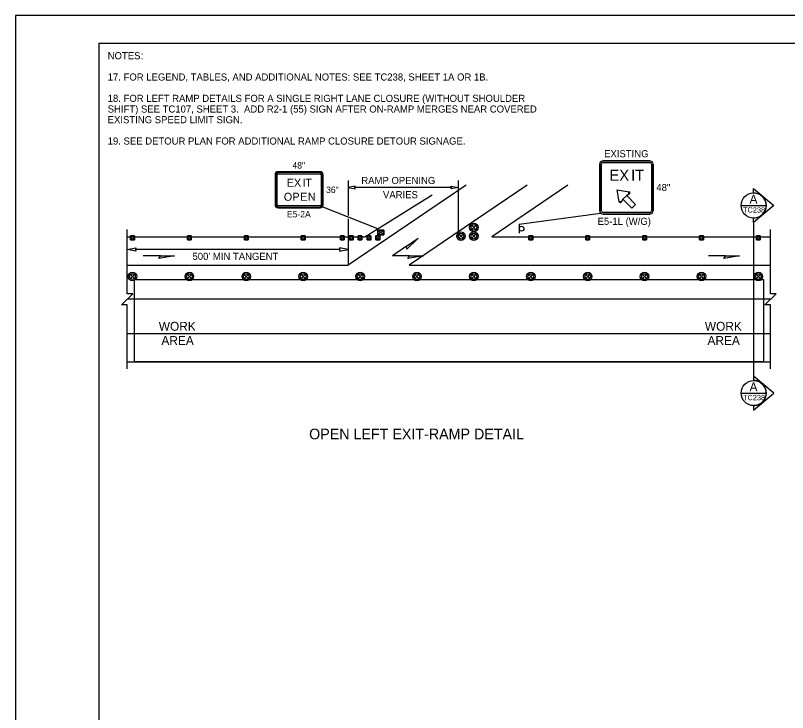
# Model space of a CAD drawing. Extents: x 99999 to 100116, y 99995 to 100013.
# Drawn here: x 100079.06 to 100087.75, y 100002.85 to 100010.69 of the extents above; entities that cross this region are included whole.
import ezdxf

# ---------------------------------------------------------------- set-up
doc = ezdxf.new("R2010")
doc.units = 0
for name, color, linetype in [('RD_MK_LineEdgeYellow', 7, 'Continuous'), ('RD_MK_LineLane', 7, 'Continuous'), ('SH_DE_DetailHeading2Text', 7, 'Continuous'), ('SH_GI_GeneralNotesBodyText', 7, 'Continuous'), ('SH_GI_PlotLimits', 7, 'Continuous'), ('SH_GI_SheetBorder', 7, 'Continuous'), ('SH_TI_WZSectionCut', 7, 'Continuous'), ('TR_SN_ConstructionSigns', 7, 'Continuous'), ('TR_WZ_PortableSignMount5ftMinBlk-Org', 7, 'Continuous'), ('TR_WZ_TrafficCone', 7, 'Continuous'), ('TR_WZ_TrafficSafetyDrum', 7, 'Continuous'), ('TR_WZ_WorkAreaLabel', 7, 'Continuous'), ('TR_WZ_WorkZoneDetails', 7, 'Continuous'), ('TR_WZ_WorkZoneTextCurrent', 7, 'Continuous')]:
    doc.layers.add(name, color=color, linetype=linetype)

msp = doc.modelspace()

# ---------------------------------------------------------------- linework, layer by layer
at = {"layer": 'RD_MK_LineEdgeYellow'}
for p, q in [((100084.1333, 100008.7784), (100082.8064, 100007.8789)), ((100080.32, 100007.8789), (100082.8064, 100007.8789)), ((100084.4209, 100007.8789), (100087.555, 100007.8789)), ((100080.32, 100007.1109), (100087.555, 100007.1109))]:
    msp.add_line(p, q, dxfattribs=at)
at = {"layer": 'RD_MK_LineLane'}
msp.add_lwpolyline([(100087.555, 100007.4949), (100080.32, 100007.4949)], dxfattribs=at)
at = {"layer": 'SH_GI_PlotLimits'}
msp.add_lwpolyline([(100079.0625, 99999.6875), (100096.0625, 99999.6875), (100096.0625, 100010.6875), (100079.0625, 100010.6875)], close=True, dxfattribs=at)
at = {"layer": 'SH_GI_SheetBorder'}
for q in [(100080, 100000), (100095.75, 100010.375)]:
    msp.add_line((100080, 100010.375), q, dxfattribs=at)
at = {"layer": 'SH_TI_WZSectionCut'}
for p, q in [((100087.3657, 100008.6913), (100087.3657, 100008.7412)), ((100087.3657, 100008.7412), (100087.5938, 100008.55)), ((100087.5938, 100008.55), (100087.3657, 100008.3589)), ((100087.3657, 100008.3589), (100087.3657, 100008.4088)), ((100087.3657, 100008.3589), (100087.3657, 100006.6309)), ((100087.3657, 100006.6309), (100087.3657, 100006.581)), ((100087.5939, 100006.4398), (100087.3657, 100006.6309)), ((100087.3657, 100006.2486), (100087.5939, 100006.4398)), ((100087.3657, 100006.2985), (100087.3657, 100006.2486))]:
    msp.add_line(p, q, dxfattribs=at)
for points in [[(100087.2245, 100008.5501), (100087.5069, 100008.5501)], [(100087.2245, 100006.4398), (100087.5069, 100006.4398)]]:
    msp.add_lwpolyline(points, dxfattribs=at)
for centre in [(100087.3657, 100008.55), (100087.3657, 100006.4398)]:
    msp.add_circle(centre, 0.1412, dxfattribs=at)
for centre in [(100087.3657, 100008.55), (100087.3657, 100006.4398)]:
    msp.add_arc(centre, 0.1412, 269.99779, 90.00221, dxfattribs=at)
at = {"layer": 'TR_SN_ConstructionSigns'}
for p, q in [((100085.6712, 100009.0522), (100086.1962, 100009.0522)), ((100086.1962, 100009.0522), (100085.6712, 100009.0522)), ((100086.1962, 100009.0522), (100085.6712, 100009.0522)), ((100086.1962, 100009.0522), (100085.6712, 100009.0522)), ((100086.1962, 100009.0522), (100085.6712, 100009.0522)), ((100085.6712, 100009.0335), (100086.1962, 100009.0335)), ((100086.1962, 100009.0522), (100086.1962, 100009.0522)), ((100085.6337, 100008.4897), (100085.6337, 100009.0147)), ((100085.6337, 100009.0147), (100085.6337, 100009.0147)), ((100085.6337, 100009.0147), (100085.6337, 100008.4897)), ((100085.6337, 100009.0147), (100085.6337, 100008.4897)), ((100085.6337, 100009.0147), (100085.6337, 100008.4897)), ((100085.6337, 100009.0147), (100085.6337, 100008.4897)), ((100085.6525, 100008.4897), (100085.6525, 100009.0147)), ((100086.215, 100009.0147), (100086.215, 100008.4897)), ((100086.2337, 100009.0147), (100086.2337, 100008.4897)), ((100086.2337, 100008.4897), (100086.2337, 100009.0147)), ((100086.2337, 100008.4897), (100086.2337, 100009.0147)), ((100086.2337, 100008.4897), (100086.2337, 100009.0147)), ((100086.2337, 100008.4897), (100086.2337, 100009.0147)), ((100081.983, 100008.8955), (100081.983, 100008.558)), ((100081.9914, 100008.8955), (100081.9914, 100008.558)), ((100082.0055, 100008.558), (100082.0055, 100008.8955)), ((100082.4893, 100008.9292), (100082.0168, 100008.9292)), ((100082.4893, 100008.9208), (100082.0168, 100008.9208)), ((100082.0168, 100008.9067), (100082.4893, 100008.9067)), ((100082.5005, 100008.8955), (100082.5005, 100008.558)), ((100082.5146, 100008.558), (100082.5146, 100008.8955)), ((100082.523, 100008.558), (100082.523, 100008.8955)), ((100085.8293, 100008.7277), (100085.9652, 100008.7029)), ((100085.8541, 100008.5918), (100085.8293, 100008.7277)), ((100085.9688, 100008.68), (100085.9376, 100008.6614)), ((100085.9652, 100008.7029), (100085.9624, 100008.6907)), ((100085.9624, 100008.6907), (100085.9652, 100008.7029)), ((100085.9624, 100008.6907), (100085.9688, 100008.68)), ((100085.9688, 100008.68), (100085.9624, 100008.6907)), ((100085.8663, 100008.5946), (100085.8541, 100008.5918)), ((100085.8541, 100008.5918), (100085.8663, 100008.5946)), ((100085.8771, 100008.5882), (100085.8663, 100008.5946)), ((100085.8663, 100008.5946), (100085.8771, 100008.5882)), ((100085.8956, 100008.6195), (100085.8771, 100008.5882)), ((100085.8956, 100008.6195), (100085.9376, 100008.6614)), ((100085.9376, 100008.6614), (100085.8956, 100008.6195)), ((100085.9961, 100008.5189), (100085.8956, 100008.6195)), ((100085.9376, 100008.6614), (100086.0381, 100008.5609)), ((100082.4893, 100008.5467), (100082.0168, 100008.5467)), ((100082.0168, 100008.5327), (100082.4893, 100008.5327)), ((100082.0168, 100008.5242), (100082.4893, 100008.5242)), ((100086.0381, 100008.5609), (100085.9961, 100008.5189)), ((100086.1962, 100008.471), (100085.6712, 100008.471)), ((100086.1962, 100008.4522), (100085.6712, 100008.4522)), ((100085.6712, 100008.4522), (100085.6712, 100008.4522)), ((100085.6712, 100008.4522), (100086.1962, 100008.4522)), ((100085.6712, 100008.4522), (100086.1962, 100008.4522)), ((100085.6712, 100008.4522), (100086.1962, 100008.4522)), ((100086.2337, 100008.4897), (100086.2337, 100008.4897))]:
    msp.add_line(p, q, dxfattribs=at)
for points in [[(100085.6712, 100008.4522), (100085.6712, 100008.4522)], [(100085.6712, 100008.4522), (100086.1962, 100008.4522), (100086.1962, 100008.4522)]]:
    msp.add_lwpolyline(points, dxfattribs=at)
for centre, radius, start, end in [((100085.6712, 100009.0147), 0.0375, 90, 180.00001), ((100085.6712, 100009.0147), 0.0375, 90, 180), ((100085.6712, 100009.0147), 0.0375, 90, 180), ((100085.6712, 100009.0147), 0.0375, 90, 180), ((100085.6712, 100009.0147), 0.0375, 90, 180), ((100085.6712, 100009.0147), 0.0187, 90, 180.00001), ((100086.1962, 100009.0147), 0.0375, 0, 90), ((100086.1962, 100009.0147), 0.0375, 0, 90), ((100086.1962, 100009.0147), 0.0375, 0, 90), ((100086.1962, 100009.0147), 0.0375, 0, 90), ((100086.1962, 100009.0147), 0.0375, 0, 90), ((100086.1962, 100009.0147), 0.0187, 0, 90), ((100082.0168, 100008.8955), 0.0338, 90, 180), ((100082.0168, 100008.8955), 0.0253, 90, 180.00001), ((100082.0168, 100008.8955), 0.0112, 90, 180.00001), ((100082.4893, 100008.8955), 0.0338, 360, 90), ((100082.4893, 100008.8955), 0.0253, 360, 90), ((100082.4893, 100008.8955), 0.0112, 360, 90), ((100085.9624, 100008.6907), 0.0125, 300.67412, 77.22876), ((100085.8663, 100008.5946), 0.0125, 192.77123, 329.32586), ((100082.0168, 100008.558), 0.0338, 180, 270.00001), ((100082.0168, 100008.558), 0.0253, 180.00001, 270), ((100082.0168, 100008.558), 0.0112, 180.00001, 270), ((100082.4893, 100008.558), 0.0338, 270.00001, 0.00001), ((100082.4893, 100008.558), 0.0253, 270, 0.00001), ((100082.4893, 100008.558), 0.0112, 270, 0.00001), ((100085.6712, 100008.4897), 0.0375, 180.00001, 270), ((100085.6712, 100008.4897), 0.0375, 180, 270.00001), ((100085.6712, 100008.4897), 0.0375, 180, 270.00001), ((100085.6712, 100008.4897), 0.0375, 180, 270), ((100085.6712, 100008.4897), 0.0375, 180, 270.00001), ((100085.6712, 100008.4897), 0.0187, 180.00001, 270), ((100086.1962, 100008.4897), 0.0375, 270, 0.00001), ((100086.1962, 100008.4897), 0.0375, 270.00001, 0.00001), ((100086.1962, 100008.4897), 0.0375, 270.00001, 0.00001), ((100086.1962, 100008.4897), 0.0375, 270.00001, 0.00001), ((100086.1962, 100008.4897), 0.0187, 270, 0.00001), ((100086.1962, 100008.4897), 0.0375, 270.00001, 0.00001)]:
    msp.add_arc(centre, radius, start, end, dxfattribs=at)
at = {"layer": 'TR_WZ_PortableSignMount5ftMinBlk-Org'}
for p, q in [((100083.1389, 100008.2069), (100083.1389, 100008.2869)), ((100083.2056, 100008.2729), (100083.1389, 100008.2209)), ((100083.2056, 100008.2209), (100083.1389, 100008.2729)), ((100083.1723, 100008.2469), (100083.1723, 100008.2469)), ((100083.1724, 100008.247), (100083.1724, 100008.247))]:
    msp.add_line(p, q, dxfattribs=at)
for points in [[(100083.2056, 100008.2729), (100083.2056, 100008.2209), (100083.1389, 100008.2209), (100083.1389, 100008.2729)], [(100083.1389, 100008.2209), (100083.2056, 100008.2209), (100083.2056, 100008.2729), (100083.1389, 100008.2729)]]:
    msp.add_lwpolyline(points, close=True, dxfattribs=at)
at = {"layer": 'TR_WZ_TrafficCone'}
for points in [[(100080.3576, 100008.1642), (100080.4003, 100008.1642), (100080.4003, 100008.2069), (100080.3576, 100008.2069), (100080.3576, 100008.1642)], [(100080.3576, 100008.2069), (100080.4003, 100008.2069), (100080.4003, 100008.1642), (100080.3576, 100008.1642), (100080.3576, 100008.2069)], [(100080.9976, 100008.1642), (100081.0403, 100008.1642), (100081.0403, 100008.2069), (100080.9976, 100008.2069), (100080.9976, 100008.1642)], [(100080.9976, 100008.2069), (100081.0403, 100008.2069), (100081.0403, 100008.1642), (100080.9976, 100008.1642), (100080.9976, 100008.2069)], [(100081.6376, 100008.1642), (100081.6803, 100008.1642), (100081.6803, 100008.2069), (100081.6376, 100008.2069), (100081.6376, 100008.1642)], [(100081.6376, 100008.2069), (100081.6803, 100008.2069), (100081.6803, 100008.1642), (100081.6376, 100008.1642), (100081.6376, 100008.2069)], [(100082.2776, 100008.1642), (100082.3203, 100008.1642), (100082.3203, 100008.2069), (100082.2776, 100008.2069), (100082.2776, 100008.1642)], [(100082.2776, 100008.2069), (100082.3203, 100008.2069), (100082.3203, 100008.1642), (100082.2776, 100008.1642), (100082.2776, 100008.2069)], [(100082.7176, 100008.1642), (100082.7603, 100008.1642), (100082.7603, 100008.2069), (100082.7176, 100008.2069), (100082.7176, 100008.1642)], [(100082.7176, 100008.2069), (100082.7603, 100008.2069), (100082.7603, 100008.1642), (100082.7176, 100008.1642), (100082.7176, 100008.2069)], [(100082.8176, 100008.1642), (100082.8603, 100008.1642), (100082.8603, 100008.2069), (100082.8176, 100008.2069), (100082.8176, 100008.1642)], [(100082.8176, 100008.2069), (100082.8603, 100008.2069), (100082.8603, 100008.1642), (100082.8176, 100008.1642), (100082.8176, 100008.2069)], [(100082.9176, 100008.1642), (100082.9603, 100008.1642), (100082.9603, 100008.2069), (100082.9176, 100008.2069), (100082.9176, 100008.1642)], [(100082.9176, 100008.2069), (100082.9603, 100008.2069), (100082.9603, 100008.1642), (100082.9176, 100008.1642), (100082.9176, 100008.2069)], [(100083.0176, 100008.1642), (100083.0603, 100008.1642), (100083.0603, 100008.2069), (100083.0176, 100008.2069), (100083.0176, 100008.1642)], [(100083.0176, 100008.2069), (100083.0603, 100008.2069), (100083.0603, 100008.1642), (100083.0176, 100008.1642), (100083.0176, 100008.2069)], [(100083.1176, 100008.1642), (100083.1603, 100008.1642), (100083.1603, 100008.2069), (100083.1176, 100008.2069), (100083.1176, 100008.1642)], [(100083.1176, 100008.2069), (100083.1603, 100008.2069), (100083.1603, 100008.1642), (100083.1176, 100008.1642), (100083.1176, 100008.2069)], [(100084.8376, 100008.1642), (100084.8803, 100008.1642), (100084.8803, 100008.2069), (100084.8376, 100008.2069), (100084.8376, 100008.1642)], [(100084.8376, 100008.2069), (100084.8803, 100008.2069), (100084.8803, 100008.1642), (100084.8376, 100008.1642), (100084.8376, 100008.2069)], [(100085.4776, 100008.1642), (100085.5203, 100008.1642), (100085.5203, 100008.2069), (100085.4776, 100008.2069), (100085.4776, 100008.1642)], [(100085.4776, 100008.2069), (100085.5203, 100008.2069), (100085.5203, 100008.1642), (100085.4776, 100008.1642), (100085.4776, 100008.2069)], [(100086.1176, 100008.1642), (100086.1603, 100008.1642), (100086.1603, 100008.2069), (100086.1176, 100008.2069), (100086.1176, 100008.1642)], [(100086.1176, 100008.2069), (100086.1603, 100008.2069), (100086.1603, 100008.1642), (100086.1176, 100008.1642), (100086.1176, 100008.2069)], [(100086.7576, 100008.1642), (100086.8003, 100008.1642), (100086.8003, 100008.2069), (100086.7576, 100008.2069), (100086.7576, 100008.1642)], [(100086.7576, 100008.2069), (100086.8003, 100008.2069), (100086.8003, 100008.1642), (100086.7576, 100008.1642), (100086.7576, 100008.2069)], [(100087.3976, 100008.1642), (100087.4403, 100008.1642), (100087.4403, 100008.2069), (100087.3976, 100008.2069), (100087.3976, 100008.1642)], [(100087.3976, 100008.2069), (100087.4403, 100008.2069), (100087.4403, 100008.1642), (100087.3976, 100008.1642), (100087.3976, 100008.2069)]]:
    msp.add_lwpolyline(points, dxfattribs=at)
for centre in [(100080.3789, 100008.1856), (100081.0189, 100008.1856), (100081.6589, 100008.1856), (100082.2989, 100008.1856), (100082.7389, 100008.1856), (100082.8389, 100008.1856), (100082.9389, 100008.1856), (100083.0389, 100008.1856), (100083.1389, 100008.1856), (100084.8589, 100008.1856), (100085.4989, 100008.1856), (100086.1389, 100008.1856), (100086.7789, 100008.1856), (100087.4189, 100008.1856)]:
    msp.add_circle(centre, 0.0133, dxfattribs=at)
at = {"layer": 'TR_WZ_TrafficSafetyDrum'}
for p, q in [((100084.1963, 100008.3252), (100084.2415, 100008.2799)), ((100084.2415, 100008.3252), (100084.1963, 100008.2799)), ((100084.0513, 100008.2269), (100084.0965, 100008.1816)), ((100084.0965, 100008.2269), (100084.0513, 100008.1816)), ((100084.1963, 100008.2269), (100084.2415, 100008.1816)), ((100084.2415, 100008.2269), (100084.1963, 100008.1816)), ((100080.3563, 100007.7735), (100080.4015, 100007.7283)), ((100080.4015, 100007.7735), (100080.3563, 100007.7283)), ((100080.9963, 100007.7735), (100081.0415, 100007.7283)), ((100081.0415, 100007.7735), (100080.9963, 100007.7283)), ((100081.6363, 100007.7735), (100081.6815, 100007.7283)), ((100081.6815, 100007.7735), (100081.6363, 100007.7283)), ((100082.2763, 100007.7735), (100082.3215, 100007.7283)), ((100082.3215, 100007.7735), (100082.2763, 100007.7283)), ((100082.9163, 100007.7735), (100082.9615, 100007.7283)), ((100082.9615, 100007.7735), (100082.9163, 100007.7283)), ((100083.5563, 100007.7735), (100083.6015, 100007.7283)), ((100083.6015, 100007.7735), (100083.5563, 100007.7283)), ((100084.1963, 100007.7735), (100084.2415, 100007.7283)), ((100084.2415, 100007.7735), (100084.1963, 100007.7283)), ((100084.8363, 100007.7735), (100084.8815, 100007.7283)), ((100084.8815, 100007.7735), (100084.8363, 100007.7283)), ((100085.4763, 100007.7735), (100085.5215, 100007.7283)), ((100085.5215, 100007.7735), (100085.4763, 100007.7283)), ((100086.1163, 100007.7735), (100086.1615, 100007.7283)), ((100086.1615, 100007.7735), (100086.1163, 100007.7283)), ((100086.7563, 100007.7735), (100086.8015, 100007.7283)), ((100086.8015, 100007.7735), (100086.7563, 100007.7283)), ((100087.3963, 100007.7735), (100087.4415, 100007.7283)), ((100087.4415, 100007.7735), (100087.3963, 100007.7283))]:
    msp.add_line(p, q, dxfattribs=at)
for centre, radius in [((100084.2189, 100008.3025), 0.048), ((100084.2189, 100008.3025), 0.048), ((100084.2189, 100008.3025), 0.032), ((100084.0739, 100008.2042), 0.048), ((100084.0739, 100008.2042), 0.048), ((100084.2189, 100008.2042), 0.048), ((100084.2189, 100008.2042), 0.048), ((100084.0739, 100008.2042), 0.032), ((100084.2189, 100008.2042), 0.032), ((100080.3789, 100007.7509), 0.048), ((100080.3789, 100007.7509), 0.048), ((100080.3789, 100007.7509), 0.032), ((100081.0189, 100007.7509), 0.048), ((100081.0189, 100007.7509), 0.048), ((100081.0189, 100007.7509), 0.032), ((100081.6589, 100007.7509), 0.048), ((100081.6589, 100007.7509), 0.048), ((100081.6589, 100007.7509), 0.032), ((100082.2989, 100007.7509), 0.048), ((100082.2989, 100007.7509), 0.048), ((100082.2989, 100007.7509), 0.032), ((100082.9389, 100007.7509), 0.048), ((100082.9389, 100007.7509), 0.048), ((100082.9389, 100007.7509), 0.032), ((100083.5789, 100007.7509), 0.048), ((100083.5789, 100007.7509), 0.048), ((100083.5789, 100007.7509), 0.032), ((100084.2189, 100007.7509), 0.048), ((100084.2189, 100007.7509), 0.048), ((100084.2189, 100007.7509), 0.032), ((100084.8589, 100007.7509), 0.048), ((100084.8589, 100007.7509), 0.048), ((100084.8589, 100007.7509), 0.032), ((100085.4989, 100007.7509), 0.048), ((100085.4989, 100007.7509), 0.048), ((100085.4989, 100007.7509), 0.032), ((100086.1389, 100007.7509), 0.048), ((100086.1389, 100007.7509), 0.048), ((100086.1389, 100007.7509), 0.032), ((100086.7789, 100007.7509), 0.048), ((100086.7789, 100007.7509), 0.048), ((100086.7789, 100007.7509), 0.032), ((100087.4189, 100007.7509), 0.048), ((100087.4189, 100007.7509), 0.048), ((100087.4189, 100007.7509), 0.032)]:
    msp.add_circle(centre, radius, dxfattribs=at)
at = {"layer": 'TR_WZ_WorkZoneDetails'}
for p, q in [((100082.8064, 100008.8313), (100082.8064, 100008.4391)), ((100084.8178, 100008.7784), (100083.9935, 100008.2196)), ((100084.0419, 100008.8313), (100084.0419, 100008.1936)), ((100085.2753, 100008.7784), (100084.4209, 100008.1989)), ((100083.9669, 100008.7513), (100082.8814, 100008.7513)), ((100082.9928, 100008.1989), (100083.7508, 100008.6713)), ((100083.1389, 100008.2869), (100082.5131, 100008.5341)), ((100084.7282, 100008.3389), (100085.6447, 100008.4632)), ((100082.8064, 100008.3991), (100082.8064, 100007.8789)), ((100084.7282, 100008.3389), (100084.7282, 100008.2389)), ((100080.32, 100008.1989), (100082.9928, 100008.1989)), ((100083.9935, 100008.2196), (100083.4908, 100007.8789)), ((100084.4209, 100008.1989), (100087.555, 100008.1989)), ((100083.4618, 100008.0932), (100083.3021, 100007.985)), ((100082.7126, 100008.0559), (100080.4137, 100008.0559)), ((100080.6926, 100007.985), (100080.4997, 100007.985)), ((100083.495, 100007.985), (100083.3021, 100007.985)), ((100087.0492, 100007.985), (100086.8563, 100007.985)), ((100083.4908, 100007.8789), (100084.4209, 100007.8789)), ((100080.32, 100006.7909), (100087.555, 100006.7909))]:
    msp.add_line(p, q, dxfattribs=at)
for points in [[(100082.8064, 100008.7513), (100082.885, 100008.7359), (100082.8814, 100008.7513), (100082.885, 100008.7667)], [(100084.0419, 100008.7513), (100083.9633, 100008.7359), (100083.9669, 100008.7513), (100083.9633, 100008.7667)], [(100083.592, 100008.1814), (100083.4644, 100008.0577), (100083.4618, 100008.0932)], [(100080.32, 100008.0559), (100080.4183, 100008.0751), (100080.4137, 100008.0559), (100080.4183, 100008.0366)], [(100082.8063, 100008.0559), (100082.7081, 100008.0751), (100082.7126, 100008.0559), (100082.7081, 100008.0366)], [(100080.8498, 100007.985), (100080.6747, 100007.9541), (100080.6926, 100007.985)], [(100083.6523, 100007.985), (100083.4772, 100007.9541), (100083.495, 100007.985)], [(100087.2065, 100007.985), (100087.0314, 100007.9541), (100087.0492, 100007.985)], [(100080.4, 100006.7909), (100080.4, 100007.7189), (100087.475, 100007.7189), (100087.475, 100006.7909)]]:
    msp.add_lwpolyline(points, close=True, dxfattribs=at)
for points in [[(100080.32, 100006.7109), (100080.32, 100007.433), (100080.256, 100007.433), (100080.384, 100007.5569), (100080.32, 100007.5569), (100080.32, 100008.2789)], [(100087.555, 100006.7109), (100087.555, 100007.433), (100087.491, 100007.433), (100087.619, 100007.5569), (100087.555, 100007.5569), (100087.555, 100008.2789)]]:
    msp.add_lwpolyline(points, dxfattribs=at)
msp.add_circle((100084.7552, 100008.2888), 0.027, dxfattribs=at)
msp.add_circle((100084.7552, 100008.2888), 0.027, dxfattribs=at)

# ---------------------------------------------------------------- texts
at = {"layer": 'SH_DE_DetailHeading2Text'}
msp.add_text('OPEN LEFT EXIT-RAMP DETAIL', height=0.12, rotation=360, dxfattribs=at).set_placement((100082.3657, 100005.9196))
at = {"layer": 'SH_GI_GeneralNotesBodyText'}
for s, p in [('NOTES', (100080.1, 100010.195)), (':', (100080.4743, 100010.195)), ('17. FOR LEGEND, TABLES, AND ADDITIONAL NOTES: SEE TC238, SHEET 1A OR 1B.', (100080.1, 100009.955)), ('18. FOR LEFT RAMP DETAILS FOR A SINGLE RIGHT LANE CLOSURE (WITHOUT SHOULDER ', (100080.1, 100009.715)), ('SHIFT) SEE TC107, SHEET 3.  ADD R2-1 (55) SIGN AFTER ON-RAMP MERGES NEAR COVERED ', (100080.1, 100009.595)), ('EXISTING SPEED LIMIT SIGN.', (100080.1, 100009.475)), ('19. SEE DETOUR PLAN FOR ADDITIONAL RAMP CLOSURE DETOUR SIGNAGE.', (100080.1, 100009.235))]:
    msp.add_text(s, height=0.08, rotation=360, dxfattribs=at).set_placement(p)
at = {"layer": 'SH_TI_WZSectionCut'}
for s, height, rotation, p in [('A', 0.1, 0.00995, (100087.3195, 100008.5707)), ('TC238', 0.06, 360, (100087.2459, 100008.4701)), ('A', 0.1, 0.00995, (100087.3195, 100006.4604)), ('TC238', 0.06, 360, (100087.2459, 100006.3598))]:
    msp.add_text(s, height=height, rotation=rotation, dxfattribs=at).set_placement(p)
at = {"layer": 'TR_SN_ConstructionSigns'}
for s, height, p in [('EXISTING', 0.08, (100085.6839, 100009.0922)), ('48"', 0.072, (100082.1782, 100008.9652)), ('E', 0.09, (100082.1153, 100008.7605)), ('X', 0.09, (100082.1954, 100008.7605)), ('I', 0.09, (100082.2917, 100008.7605)), ('T', 0.09, (100082.3232, 100008.7605)), ('36"', 0.072, (100082.5568, 100008.6907)), ('48"', 0.08, (100086.2713, 100008.7122)), ('O', 0.09, (100082.0816, 100008.603)), ('P', 0.09, (100082.1779, 100008.603)), ('E', 0.09, (100082.2661, 100008.603)), ('N', 0.09, (100082.3516, 100008.603)), ('E5-2A', 0.072, (100082.1164, 100008.4162)), ('E5-1L (W/G)', 0.08, (100085.6101, 100008.3322))]:
    msp.add_text(s, height=height, rotation=360, dxfattribs=at).set_placement(p)
for s, p in [('E', (100085.7425, 100008.8277)), ('X', (100085.8537, 100008.8277)), ('I', (100085.9875, 100008.8277)), ('T', (100086.0312, 100008.8277))]:
    msp.add_text(s, height=0.125, dxfattribs=at).set_placement(p)
at = {"layer": 'TR_WZ_WorkAreaLabel'}
for s, p in [('WORK', (100080.6746, 100007.1409)), ('WORK', (100086.8169, 100007.1409)), ('AREA', (100080.7043, 100006.9809)), ('AREA', (100086.8465, 100006.9809))]:
    msp.add_text(s, height=0.1, dxfattribs=at).set_placement(p)
at = {"layer": 'TR_WZ_WorkZoneTextCurrent'}
for s, p in [('RAMP OPENING', (100082.9527, 100008.7913)), ('VARIES', (100083.1965, 100008.6313)), ("500' MIN TANGENT", (100081.0542, 100007.9379))]:
    msp.add_text(s, height=0.08, dxfattribs=at).set_placement(p)

doc.saveas('drawing.dxf')
